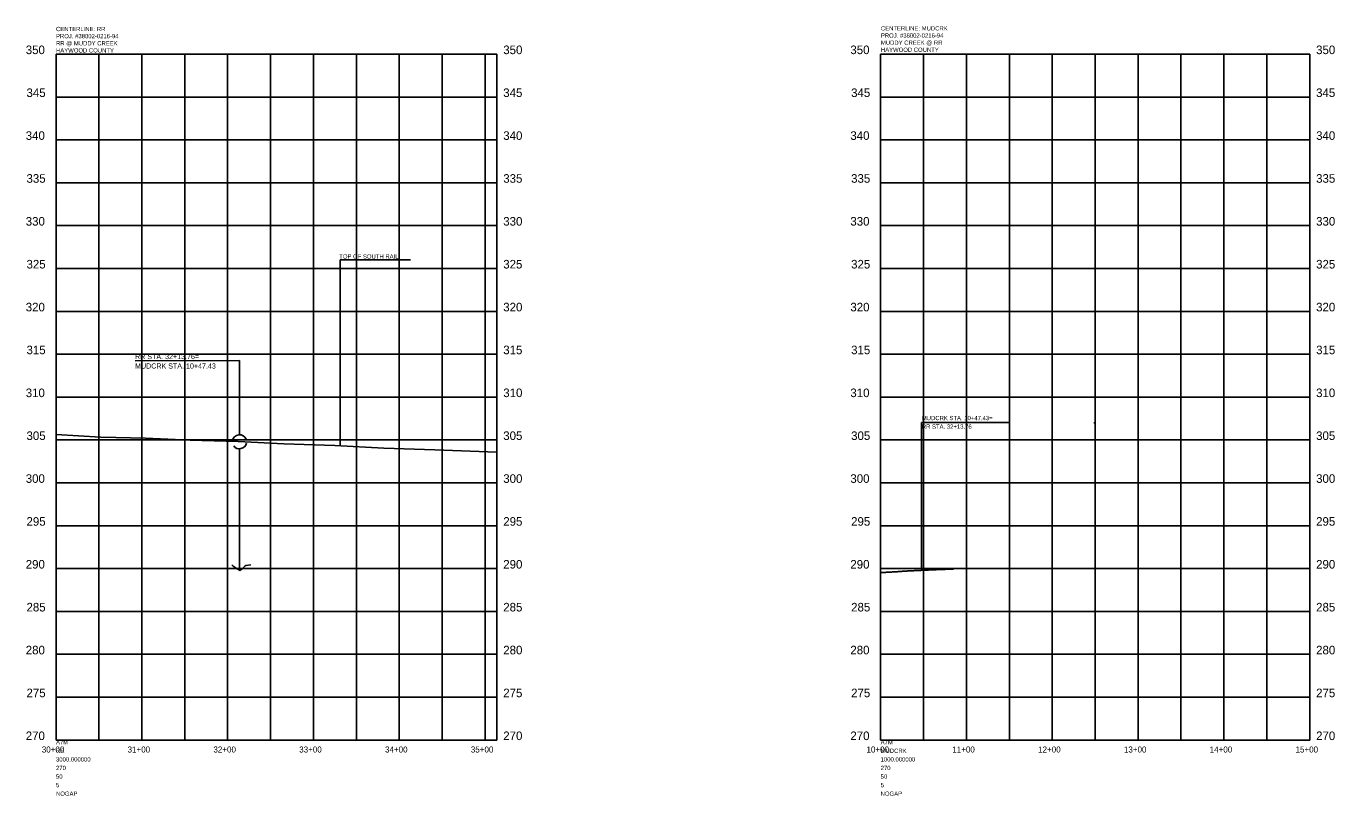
# Model space of a CAD drawing. Extents: x -200 to 949611, y -218 to 425120.
# Drawn here: x 945505 to 947030, y 423666 to 424564 of the extents above; entities that cross this region are included whole.
import ezdxf

# ---------------------------------------------------------------- set-up
doc = ezdxf.new("R2010")
doc.units = 0
for name, color, linetype in [('DESIGN - SHEET - Corner Text', 7, 'Continuous'), ('DESIGN - SHEET - Light Grid', 7, 'Continuous'), ('SURVEY - PROFILE - Drainage - Bridge Hydraulic Data with Text', 7, 'Continuous'), ('SURVEY - PROFILE - Existing Roads with Text', 7, 'Continuous'), ('SURVEY - PROFILE - Project Information and Notes', 7, 'Continuous')]:
    doc.layers.add(name, color=color, linetype=linetype)

msp = doc.modelspace()

# ---------------------------------------------------------------- linework, layer by layer
at = {"layer": 'DESIGN - SHEET - Light Grid'}
for p, q in [((946053.5, 424531.5), (945539.8, 424531.5)), ((945539.8, 424531.5), (945539.8, 423731.5)), ((945539.8, 423731.5), (945539.8, 424531.5)), ((945589.8, 423731.5), (945589.8, 424531.5)), ((945639.8, 423731.5), (945639.8, 424531.5)), ((945689.8, 423731.5), (945689.8, 424531.5)), ((945739.8, 423731.5), (945739.8, 424531.5)), ((945789.8, 423731.5), (945789.8, 424531.5)), ((945839.8, 423731.5), (945839.8, 424531.5)), ((945889.8, 423731.5), (945889.8, 424531.5)), ((945939.8, 423731.5), (945939.8, 424531.5)), ((945989.8, 423731.5), (945989.8, 424531.5)), ((946039.8, 423731.5), (946039.8, 424531.5)), ((946053.5, 423731.5), (946053.5, 424531.5)), ((947000.8, 424531.5), (946500.8, 424531.5)), ((946500.8, 424531.5), (946500.8, 423731.5)), ((946500.8, 423731.5), (946500.8, 424531.5)), ((946550.8, 423731.5), (946550.8, 424531.5)), ((946600.8, 423731.5), (946600.8, 424531.5)), ((946650.8, 423731.5), (946650.8, 424531.5)), ((946700.8, 423731.5), (946700.8, 424531.5)), ((946750.8, 423731.5), (946750.8, 424531.5)), ((946800.8, 423731.5), (946800.8, 424531.5)), ((946850.8, 423731.5), (946850.8, 424531.5)), ((946900.8, 423731.5), (946900.8, 424531.5)), ((946950.8, 423731.5), (946950.8, 424531.5)), ((947000.8, 423731.5), (947000.8, 424531.5)), ((945539.8, 424481.5), (946053.5, 424481.5)), ((946500.8, 424481.5), (947000.8, 424481.5)), ((945539.8, 424431.5), (946053.5, 424431.5)), ((946500.8, 424431.5), (947000.8, 424431.5)), ((945539.8, 424381.5), (946053.5, 424381.5)), ((946500.8, 424381.5), (947000.8, 424381.5)), ((945539.8, 424331.5), (946053.5, 424331.5)), ((946500.8, 424331.5), (947000.8, 424331.5)), ((945539.8, 424281.5), (946053.5, 424281.5)), ((946500.8, 424281.5), (947000.8, 424281.5)), ((945539.8, 424231.5), (946053.5, 424231.5)), ((946500.8, 424231.5), (947000.8, 424231.5)), ((945539.8, 424181.5), (946053.5, 424181.5)), ((946500.8, 424181.5), (947000.8, 424181.5)), ((945539.8, 424131.5), (946053.5, 424131.5)), ((946500.8, 424131.5), (947000.8, 424131.5)), ((945539.8, 424081.5), (946053.5, 424081.5)), ((946500.8, 424081.5), (947000.8, 424081.5)), ((945539.8, 424031.5), (946053.5, 424031.5)), ((946500.8, 424031.5), (947000.8, 424031.5)), ((945539.8, 423981.5), (946053.5, 423981.5)), ((946500.8, 423981.5), (947000.8, 423981.5)), ((945539.8, 423931.5), (946053.5, 423931.5)), ((946500.8, 423931.5), (947000.8, 423931.5)), ((945539.8, 423881.5), (946053.5, 423881.5)), ((946500.8, 423881.5), (947000.8, 423881.5)), ((945539.8, 423831.5), (946053.5, 423831.5)), ((946500.8, 423831.5), (947000.8, 423831.5)), ((945539.8, 423781.5), (946053.5, 423781.5)), ((946500.8, 423781.5), (947000.8, 423781.5)), ((945539.8, 423731.5), (946053.5, 423731.5)), ((945539.8, 423731.5), (946053.5, 423731.5)), ((945539.8, 423731.5), (945539.8, 423731.5)), ((946500.8, 423731.5), (947000.8, 423731.5)), ((946500.8, 423731.5), (946585.8, 423731.5)), ((946500.8, 423731.5), (946500.8, 423731.5))]:
    msp.add_line(p, q, dxfattribs=at)
at = {"layer": 'SURVEY - PROFILE - Drainage - Bridge Hydraulic Data with Text'}
for points in [[(945744.8, 423935.8), (945746.3, 423934.5), (945748.7, 423932.8), (945749.8, 423932.1), (945751.1, 423931.2), (945753.5, 423929.5), (945754.1, 423929.1), (945755.3, 423930.2), (945755.7, 423930.5), (945757, 423931.7), (945757.9, 423932.5), (945758.6, 423933.2), (945760.3, 423934.6), (945760.9, 423935.1), (945767, 423935.9)], [(946500.8, 423926.8), (946501.4, 423926.8), (946501.9, 423926.8), (946502.4, 423926.9), (946502.9, 423926.9), (946503.4, 423926.9), (946503.9, 423927), (946504.4, 423927), (946504.9, 423927), (946505.4, 423927), (946505.9, 423927.1), (946506.4, 423927.1), (946506.9, 423927.1), (946507.4, 423927.2), (946507.9, 423927.2), (946508.4, 423927.2), (946508.9, 423927.2), (946509.4, 423927.3), (946509.9, 423927.3), (946510.4, 423927.3), (946510.9, 423927.4), (946511.4, 423927.4), (946511.9, 423927.4), (946512.4, 423927.5), (946512.9, 423927.5), (946513.4, 423927.5), (946513.9, 423927.5), (946514.4, 423927.6), (946514.9, 423927.6), (946515.4, 423927.6), (946515.9, 423927.7), (946516.4, 423927.7), (946516.9, 423927.7), (946517.4, 423927.8), (946517.9, 423927.8), (946518.4, 423927.8), (946518.9, 423927.8), (946519.4, 423927.9), (946519.9, 423927.9), (946520.4, 423927.9), (946520.9, 423928), (946521.4, 423928), (946521.9, 423928), (946522.4, 423928.1), (946522.9, 423928.1), (946523.4, 423928.1), (946523.9, 423928.1), (946524.4, 423928.2), (946524.9, 423928.2), (946525.4, 423928.2), (946525.9, 423928.3), (946526.4, 423928.3), (946526.9, 423928.3), (946527.4, 423928.4), (946527.9, 423928.4), (946528.4, 423928.4), (946528.8, 423928.5), (946529.1, 423928.5), (946529.8, 423928.5), (946530.3, 423928.6), (946530.8, 423928.6), (946531.3, 423928.6), (946531.8, 423928.6), (946532.3, 423928.7), (946532.8, 423928.7), (946533.3, 423928.7), (946533.8, 423928.7), (946534.3, 423928.8), (946534.8, 423928.8), (946535.3, 423928.8), (946535.8, 423928.8), (946536.3, 423928.9), (946536.8, 423928.9), (946537.3, 423928.9), (946537.8, 423929), (946538.3, 423929), (946538.8, 423929), (946539.3, 423929), (946539.8, 423929.1), (946540.3, 423929.1), (946540.8, 423929.1), (946541.3, 423929.1), (946541.8, 423929.2), (946542.3, 423929.2), (946542.8, 423929.2), (946543.3, 423929.2), (946543.8, 423929.3), (946544.3, 423929.3), (946544.8, 423929.3), (946545.3, 423929.3), (946545.8, 423929.3), (946546.3, 423929.4), (946546.8, 423929.4), (946547.3, 423929.4), (946547.8, 423929.4), (946548.3, 423929.5), (946548.8, 423929.5), (946549.3, 423929.5), (946549.8, 423929.5), (946550.3, 423929.6), (946550.8, 423929.6), (946551.3, 423929.6), (946551.8, 423929.6), (946552.3, 423929.7), (946552.8, 423929.7), (946553.3, 423929.7), (946553.8, 423929.7), (946554.3, 423929.8), (946554.8, 423929.8), (946555.3, 423929.8), (946555.8, 423929.8), (946556.3, 423929.8), (946556.8, 423929.9), (946557.3, 423929.9), (946557.8, 423929.9), (946558.3, 423929.9), (946558.8, 423930), (946559.3, 423930), (946559.8, 423930), (946560.3, 423930), (946560.8, 423930), (946561.3, 423930.1), (946561.8, 423930.1), (946562.3, 423930.1), (946562.8, 423930.1), (946563.3, 423930.2), (946563.8, 423930.2), (946564.3, 423930.2), (946564.8, 423930.2), (946565.3, 423930.2), (946565.8, 423930.3), (946566.3, 423930.3), (946566.8, 423930.3), (946567.3, 423930.3), (946567.8, 423930.3), (946568.3, 423930.4), (946568.8, 423930.4), (946569.3, 423930.4), (946569.8, 423930.4), (946570.3, 423930.4), (946570.8, 423930.5), (946571.3, 423930.5), (946571.8, 423930.5), (946572.3, 423930.5), (946572.8, 423930.5), (946573.3, 423930.6), (946573.8, 423930.6), (946574.3, 423930.6), (946574.8, 423930.6), (946575.3, 423930.6), (946575.8, 423930.6), (946576.3, 423930.7), (946576.8, 423930.7), (946577.3, 423930.7), (946577.8, 423930.7), (946578.3, 423930.7), (946578.8, 423930.7), (946579.3, 423930.8), (946579.8, 423930.8), (946580.3, 423930.8), (946580.8, 423930.8), (946581.3, 423930.8), (946581.8, 423930.8), (946582.3, 423930.9), (946582.8, 423930.9), (946583.3, 423930.9), (946583.8, 423930.9), (946584.3, 423930.9), (946584.8, 423930.9), (946585.3, 423930.9), (946585.8, 423930.9)]]:
    msp.add_lwpolyline(points, dxfattribs=at)
at = {"layer": 'SURVEY - PROFILE - Existing Roads with Text'}
for p, q in [((945753.6, 424174), (945632.1, 424173.9)), ((945753.6, 424174), (945753.6, 424087.6)), ((946548.3, 424102), (946548.3, 423929.5)), ((946548.3, 424102), (946650.3, 424101.8)), ((946749.2, 424101.6), (946749.5, 424101.6)), ((945753.6, 424071.1), (945753.6, 423929.5))]:
    msp.add_line(p, q, dxfattribs=at)
for points in [[(945871.1, 424074.9), (945871.1, 424291.5), (945952.9, 424291.5)], [(945539.9, 424088), (945592.2, 424084.9), (945644, 424083.7), (945696.2, 424081.4), (945752.2, 424079.6), (945805.1, 424077), (945864.7, 424075.2), (945921.9, 424072.1), (945981.1, 424070.1), (946053.5, 424067.3)]]:
    msp.add_lwpolyline(points, dxfattribs=at)
for start, end in [(21.6353, 170.8595), (216.054, 348.2867)]:
    msp.add_arc((945753.6, 424079.4), 8.22, start, end, dxfattribs=at)

# ---------------------------------------------------------------- texts
at = {"layer": 'DESIGN - SHEET - Corner Text'}
for s, height, p in [('350', 10, (945504.5, 424531.5)), ('350', 10, (946061, 424531.5)), ('350', 10, (946465.5, 424531.5)), ('350', 10, (947008.3, 424531.5)), ('345', 10, (945505.4, 424481.5)), ('345', 10, (946061, 424481.5)), ('345', 10, (946466.4, 424481.5)), ('345', 10, (947008.3, 424481.5)), ('340', 10, (945504.5, 424431.5)), ('340', 10, (946061, 424431.5)), ('340', 10, (946465.5, 424431.5)), ('340', 10, (947008.3, 424431.5)), ('335', 10, (945505.4, 424381.5)), ('335', 10, (946061, 424381.5)), ('335', 10, (946466.4, 424381.5)), ('335', 10, (947008.3, 424381.5)), ('330', 10, (945504.5, 424331.5)), ('330', 10, (946061, 424331.5)), ('330', 10, (946465.5, 424331.5)), ('330', 10, (947008.3, 424331.5)), ('325', 10, (945505.4, 424281.5)), ('325', 10, (946061, 424281.5)), ('325', 10, (946466.4, 424281.5)), ('325', 10, (947008.3, 424281.5)), ('320', 10, (945504.5, 424231.5)), ('320', 10, (946061, 424231.5)), ('320', 10, (946465.5, 424231.5)), ('320', 10, (947008.3, 424231.5)), ('315', 10, (945505.4, 424181.5)), ('315', 10, (946061, 424181.5)), ('315', 10, (946466.4, 424181.5)), ('315', 10, (947008.3, 424181.5)), ('310', 10, (945504.5, 424131.5)), ('310', 10, (946061, 424131.5)), ('310', 10, (946465.5, 424131.5)), ('310', 10, (947008.3, 424131.5)), ('305', 10, (945505.4, 424081.5)), ('305', 10, (946061, 424081.5)), ('305', 10, (946466.4, 424081.5)), ('305', 10, (947008.3, 424081.5)), ('300', 10, (945504.5, 424031.5)), ('300', 10, (946061, 424031.5)), ('300', 10, (946465.5, 424031.5)), ('300', 10, (947008.3, 424031.5)), ('295', 10, (945505.4, 423981.5)), ('295', 10, (946061, 423981.5)), ('295', 10, (946466.4, 423981.5)), ('295', 10, (947008.3, 423981.5)), ('290', 10, (945504.5, 423931.5)), ('290', 10, (946061, 423931.5)), ('290', 10, (946465.5, 423931.5)), ('290', 10, (947008.3, 423931.5)), ('285', 10, (945505.4, 423881.5)), ('285', 10, (946061, 423881.5)), ('285', 10, (946466.4, 423881.5)), ('285', 10, (947008.3, 423881.5)), ('280', 10, (945504.5, 423831.5)), ('280', 10, (946061, 423831.5)), ('280', 10, (946465.5, 423831.5)), ('280', 10, (947008.3, 423831.5)), ('275', 10, (945505.4, 423781.5)), ('275', 10, (946061, 423781.5)), ('275', 10, (946466.4, 423781.5)), ('275', 10, (947008.3, 423781.5)), ('270', 10, (945504.5, 423731.5)), ('270', 10, (946061, 423731.5)), ('270', 10, (946465.5, 423731.5)), ('270', 10, (947008.3, 423731.5)), ('30+00', 7, (945523.2, 423717)), ('31+00', 7, (945623.2, 423717)), ('32+00', 7, (945723.2, 423717)), ('33+00', 7, (945823.2, 423717)), ('34+00', 7, (945923.2, 423717)), ('35+00', 7, (946023.2, 423717)), ('10+00', 7, (946484.3, 423717)), ('11+00', 7, (946584.3, 423717)), ('12+00', 7, (946684.3, 423717)), ('13+00', 7, (946784.3, 423717)), ('14+00', 7, (946884.3, 423717)), ('15+00', 7, (946984.3, 423717))]:
    msp.add_text(s, height=height, dxfattribs=at).set_placement(p)
at = {"layer": 'DESIGN - SHEET - Light Grid'}
for s, p in [('A7M', (945539.8, 423726.5)), ('RR', (945539.8, 423716.5)), ('A7M', (946500.8, 423726.5)), ('MUDCRK', (946500.8, 423716.5)), ('3000.000000', (945539.8, 423706.5)), ('1000.000000', (946500.8, 423706.5)), ('270', (945539.8, 423696.5)), ('50', (945539.8, 423686.5)), ('50', (946500.8, 423686.5)), ('270', (946500.8, 423696.5)), ('5', (945539.8, 423676.5)), ('NOGAP', (945539.8, 423666.5)), ('5', (946500.8, 423676.5)), ('NOGAP', (946500.8, 423666.5))]:
    msp.add_text(s, height=5, dxfattribs=at).set_placement(p)
at = {"layer": 'SURVEY - PROFILE - Existing Roads with Text'}
for s, height, p in [('TOP OF SOUTH RAIL', 5, (945869.9, 424293)), ('RR STA. 32+13.76=', 6, (945631.9, 424175.8)), ('MUDCRK STA. 10+47.43', 6, (945631.9, 424164.8)), ('MUDCRK STA. 10+47.43=', 5, (946548.8, 424104.6)), ('RR STA. 32+13.76', 5, (946548.8, 424094.6))]:
    msp.add_text(s, height=height, dxfattribs=at).set_placement(p)
at = {"layer": 'SURVEY - PROFILE - Project Information and Notes'}
for s, p in [('CENTERLINE: RR', (945539.8, 424558.3)), ('CENTERLINE: MUDCRK', (946501.1, 424559.1)), ('PROJ. #38002-0216-94', (946501.1, 424550.7)), ('PROJ. #38002-0216-94', (945539.8, 424550)), ('RR @ MUDDY CREEK', (945539.8, 424541.7)), ('MUDDY CREEK @ RR', (946501.1, 424542.4)), ('HAYWOOD COUNTY', (945539.8, 424533.4)), ('HAYWOOD COUNTY', (946501.1, 424534.1))]:
    msp.add_text(s, height=4.998, dxfattribs=at).set_placement(p)

doc.saveas('drawing.dxf')
